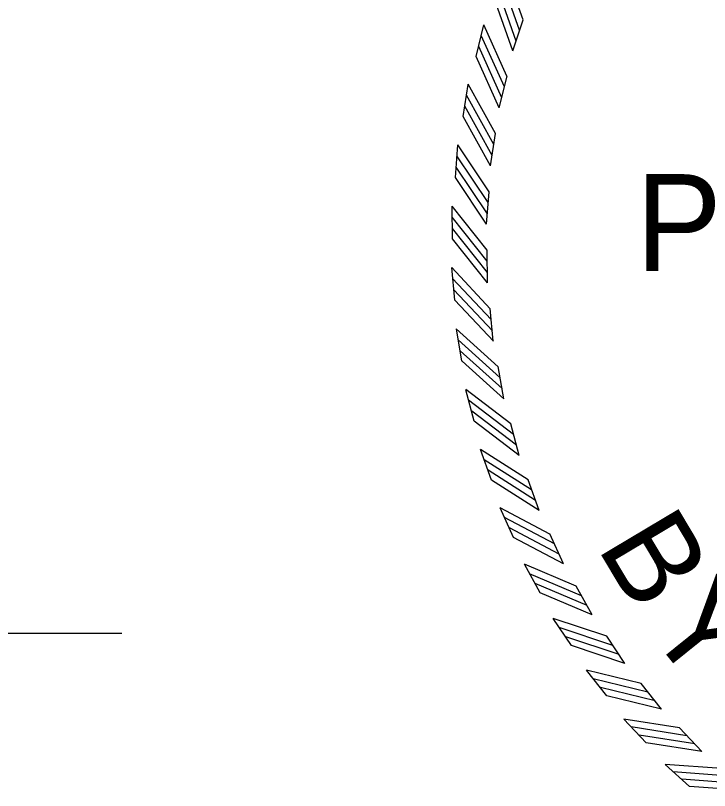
# Model space of a CAD drawing. Extents: x 166 to 3995, y -61 to 2074.
# Drawn here: x 2605.5 to 2721.4, y 445.3 to 574.8 of the extents above; entities that cross this region are included whole.
import ezdxf

# ---------------------------------------------------------------- set-up
doc = ezdxf.new("R2010")
doc.units = 0
doc.layers.add('1', color=7, linetype='Continuous')
doc.layers.add('STAMP_Byron', color=7, linetype='Continuous')

msp = doc.modelspace()

# ---------------------------------------------------------------- linework, layer by layer
at = {"layer": '1'}
msp.add_lwpolyline([(2623.24, 471.54), (2355.67, 471.54), (1787.42, 735.31), (1968.72, 681.38), (1957.17, 656.51)], dxfattribs=at)
at = {"layer": 'STAMP_Byron'}
for p, q in [((2688.54, 568.87), (2690.26, 574.05)), ((2688.54, 568.87), (2690.26, 574.05)), ((2682.42, 567.93), (2683.7, 573.22)), ((2682.42, 567.93), (2683.7, 573.22)), ((2686.29, 559.35), (2687.58, 564.65)), ((2686.29, 559.35), (2687.58, 564.65)), ((2680.26, 557.91), (2681.11, 563.28)), ((2680.26, 557.91), (2681.11, 563.28)), ((2684.83, 549.67), (2685.67, 555.06)), ((2684.83, 549.67), (2685.67, 555.06)), ((2678.94, 547.74), (2679.34, 553.16)), ((2678.94, 547.74), (2679.34, 553.16)), ((2684.17, 539.91), (2684.57, 545.34)), ((2684.17, 539.91), (2684.57, 545.34)), ((2678.47, 537.49), (2678.42, 542.93)), ((2678.47, 537.49), (2678.42, 542.93)), ((2684.32, 530.12), (2684.27, 535.57)), ((2684.32, 530.12), (2684.27, 535.57)), ((2678.84, 527.24), (2678.34, 532.66)), ((2678.84, 527.24), (2678.34, 532.66)), ((2685.28, 520.38), (2684.78, 525.81)), ((2685.28, 520.38), (2684.78, 525.81)), ((2680.05, 517.06), (2679.11, 522.42)), ((2680.05, 517.06), (2679.11, 522.42)), ((2687.04, 510.75), (2686.1, 516.12)), ((2687.04, 510.75), (2686.1, 516.12)), ((2682.11, 507.01), (2680.72, 512.27)), ((2682.11, 507.01), (2680.72, 512.27)), ((2689.59, 501.3), (2688.21, 506.58)), ((2689.59, 501.3), (2688.21, 506.58)), ((2684.98, 497.17), (2683.17, 502.29)), ((2684.98, 497.17), (2683.17, 502.29)), ((2692.92, 492.1), (2691.1, 497.24)), ((2692.92, 492.1), (2691.1, 497.24)), ((2688.66, 487.59), (2686.43, 492.55)), ((2688.66, 487.59), (2686.43, 492.55)), ((2696.99, 483.19), (2694.75, 488.17)), ((2696.99, 483.19), (2694.75, 488.17)), ((2693.12, 478.36), (2690.49, 483.12)), ((2693.12, 478.36), (2690.49, 483.12)), ((2701.78, 474.66), (2699.14, 479.43)), ((2701.78, 474.66), (2699.14, 479.43)), ((2698.32, 469.52), (2695.31, 474.05)), ((2698.32, 469.52), (2695.31, 474.05)), ((2707.26, 466.55), (2704.24, 471.09)), ((2707.26, 466.55), (2704.24, 471.09)), ((2704.24, 461.14), (2700.86, 465.4)), ((2704.24, 461.14), (2700.86, 465.4)), ((2713.39, 458.92), (2710, 463.19)), ((2713.39, 458.92), (2710, 463.19)), ((2710.83, 453.28), (2707.11, 457.25)), ((2710.83, 453.28), (2707.11, 457.25)), ((2720.13, 451.83), (2716.4, 455.8)), ((2720.13, 451.83), (2716.4, 455.8)), ((2718.04, 445.99), (2714.01, 449.64)), ((2718.04, 445.99), (2714.01, 449.64))]:
    msp.add_line(p, q, dxfattribs=at)
for points in [[(2690.26, 574.04), (2687.11, 582.92)], [(2690.26, 574.04), (2687.11, 582.92)], [(2689.67, 572.33), (2686.52, 581.2)], [(2689.67, 572.33), (2686.52, 581.2)], [(2689.11, 570.52), (2685.97, 579.39)], [(2689.11, 570.52), (2685.97, 579.39)], [(2688.54, 568.87), (2685.4, 577.74)], [(2688.54, 568.87), (2685.4, 577.74)], [(2687.57, 564.64), (2683.7, 573.22)], [(2687.57, 564.64), (2683.7, 573.22)], [(2687.13, 562.89), (2683.26, 571.47)], [(2687.13, 562.89), (2683.26, 571.47)], [(2686.72, 561.04), (2682.85, 569.62)], [(2686.72, 561.04), (2682.85, 569.62)], [(2686.29, 559.34), (2682.42, 567.92)], [(2686.29, 559.34), (2682.42, 567.92)], [(2685.67, 555.05), (2681.1, 563.29)], [(2685.67, 555.05), (2681.1, 563.29)], [(2685.37, 553.26), (2680.81, 561.5)], [(2685.37, 553.26), (2680.81, 561.5)], [(2685.12, 551.39), (2680.55, 559.62)], [(2685.12, 551.39), (2680.55, 559.62)], [(2684.83, 549.66), (2680.27, 557.9)], [(2684.83, 549.66), (2680.27, 557.9)], [(2684.57, 545.34), (2679.34, 553.17)], [(2684.57, 545.34), (2679.34, 553.17)], [(2684.42, 543.53), (2679.19, 551.36)], [(2684.42, 543.53), (2679.19, 551.36)], [(2684.32, 541.64), (2679.09, 549.47)], [(2684.32, 541.64), (2679.09, 549.47)], [(2684.17, 539.9), (2678.95, 547.73)], [(2684.17, 539.9), (2678.95, 547.73)], [(2684.27, 535.57), (2678.41, 542.94)], [(2684.27, 535.57), (2678.41, 542.94)], [(2684.27, 533.75), (2678.41, 541.12)], [(2684.27, 533.75), (2678.41, 541.12)], [(2684.33, 531.86), (2678.47, 539.23)], [(2684.33, 531.86), (2678.47, 539.23)], [(2684.33, 530.11), (2678.47, 537.48)], [(2684.33, 530.11), (2678.47, 537.48)], [(2684.78, 525.8), (2678.33, 532.66)], [(2684.78, 525.8), (2678.33, 532.66)], [(2684.93, 524), (2678.48, 530.86)], [(2684.93, 524), (2678.48, 530.86)], [(2685.14, 522.12), (2678.7, 528.98)], [(2685.14, 522.12), (2678.7, 528.98)], [(2685.29, 520.37), (2678.84, 527.23)], [(2685.29, 520.37), (2678.84, 527.23)], [(2686.09, 516.11), (2679.1, 522.42)], [(2686.09, 516.11), (2679.1, 522.42)], [(2686.39, 514.33), (2679.4, 520.63)], [(2686.39, 514.33), (2679.4, 520.63)], [(2686.76, 512.47), (2679.77, 518.78)], [(2686.76, 512.47), (2679.77, 518.78)], [(2687.05, 510.75), (2680.06, 517.05)], [(2687.05, 510.75), (2680.06, 517.05)], [(2688.21, 506.57), (2680.72, 512.28)], [(2688.21, 506.57), (2680.72, 512.28)], [(2688.65, 504.81), (2681.16, 510.52)], [(2688.65, 504.81), (2681.16, 510.52)], [(2689.17, 502.99), (2681.68, 508.7)], [(2689.17, 502.99), (2681.68, 508.7)], [(2689.6, 501.3), (2682.11, 507)], [(2689.6, 501.3), (2682.11, 507)], [(2691.1, 497.23), (2683.16, 502.3)], [(2691.1, 497.23), (2683.16, 502.3)], [(2691.69, 495.52), (2683.75, 500.58)], [(2691.69, 495.52), (2683.75, 500.58)], [(2692.35, 493.75), (2684.42, 498.82)], [(2692.35, 493.75), (2684.42, 498.82)], [(2692.92, 492.09), (2684.99, 497.16)], [(2692.92, 492.09), (2684.99, 497.16)], [(2694.75, 488.16), (2686.43, 492.56)], [(2694.75, 488.16), (2686.43, 492.56)], [(2695.48, 486.5), (2687.15, 490.9)], [(2695.48, 486.5), (2687.15, 490.9)], [(2696.29, 484.79), (2687.97, 489.19)], [(2696.29, 484.79), (2687.97, 489.19)], [(2696.99, 483.19), (2688.67, 487.59)], [(2696.99, 483.19), (2688.67, 487.59)], [(2699.14, 479.43), (2690.48, 483.12)], [(2699.14, 479.43), (2690.48, 483.12)], [(2700, 477.83), (2691.34, 481.52)], [(2700, 477.83), (2691.34, 481.52)], [(2700.95, 476.2), (2692.29, 479.89)], [(2700.95, 476.2), (2692.29, 479.89)], [(2701.79, 474.66), (2693.13, 478.35)], [(2701.79, 474.66), (2693.13, 478.35)], [(2704.24, 471.08), (2695.3, 474.05)], [(2704.24, 471.08), (2695.3, 474.05)], [(2705.23, 469.56), (2696.29, 472.53)], [(2705.23, 469.56), (2696.29, 472.53)], [(2706.31, 468.01), (2697.38, 470.98)], [(2706.31, 468.01), (2697.38, 470.98)], [(2707.27, 466.55), (2698.33, 469.51)], [(2707.27, 466.55), (2698.33, 469.51)], [(2710, 463.19), (2700.85, 465.41)], [(2710, 463.19), (2700.85, 465.41)], [(2711.12, 461.76), (2701.97, 463.97)], [(2711.12, 461.76), (2701.97, 463.97)], [(2712.32, 460.3), (2703.17, 462.52)], [(2712.32, 460.3), (2703.17, 462.52)], [(2713.4, 458.92), (2704.25, 461.14)], [(2713.4, 458.92), (2704.25, 461.14)], [(2716.4, 455.8), (2707.1, 457.25)], [(2716.4, 455.8), (2707.1, 457.25)], [(2717.63, 454.46), (2708.33, 455.92)], [(2717.63, 454.46), (2708.33, 455.92)], [(2718.95, 453.11), (2709.65, 454.57)], [(2718.95, 453.11), (2709.65, 454.57)], [(2720.14, 451.82), (2710.84, 453.28)], [(2720.14, 451.82), (2710.84, 453.28)], [(2723.39, 448.96), (2714, 449.64)], [(2723.39, 448.96), (2714, 449.64)], [(2724.72, 447.73), (2715.34, 448.41)], [(2724.72, 447.73), (2715.34, 448.41)], [(2726.15, 446.5), (2716.77, 447.18)], [(2726.15, 446.5), (2716.77, 447.18)], [(2727.44, 445.31), (2718.05, 445.99)], [(2727.44, 445.31), (2718.05, 445.99)]]:
    msp.add_lwpolyline(points, dxfattribs=at)

# ---------------------------------------------------------------- texts
msp.add_text('PROFESSIONAL', height=16.1547, dxfattribs=at).set_placement((2709.05, 532.13))
msp.add_text('PROFESSIONAL', height=16.1547, dxfattribs=at).set_placement((2709.05, 532.13))
for s, rotation, p in [('B', 300.7985, (2702.47, 486.04)), ('B', 300.7985, (2702.47, 486.04)), ('Y', 308.8241, (2710.55, 472.49)), ('Y', 308.8241, (2710.55, 472.49))]:
    msp.add_text(s, height=15.03, rotation=rotation, dxfattribs=at).set_placement(p)

doc.saveas('drawing.dxf')
